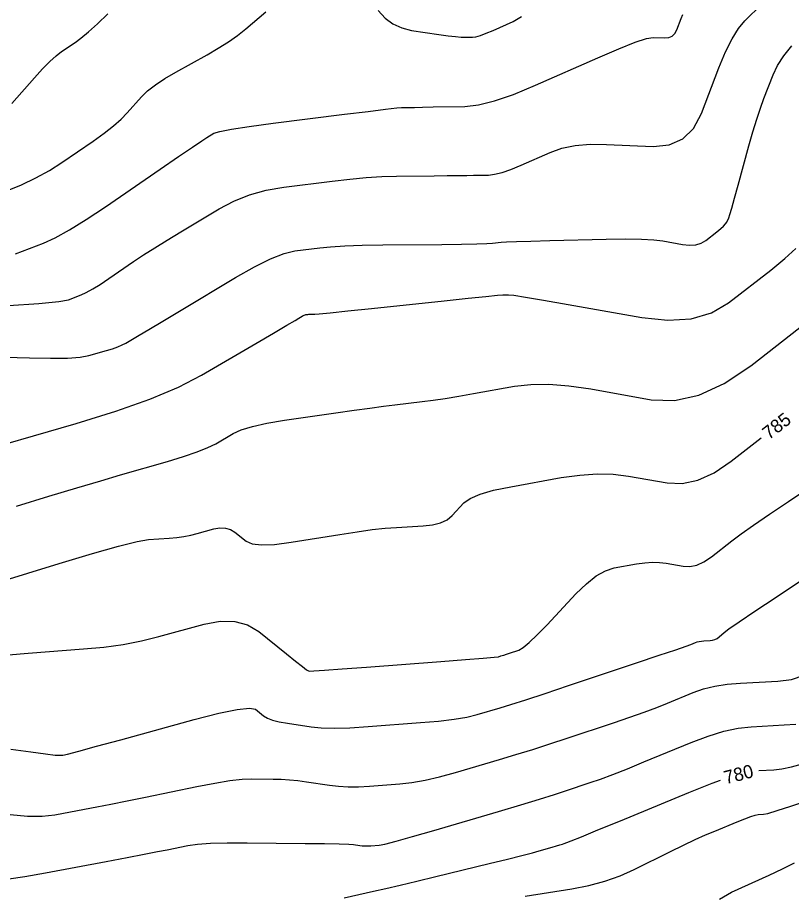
# Model space of a CAD drawing. Extents: x 2082232 to 2083549, y 592624 to 593832.
# Drawn here: x 2082483.95 to 2082524.73, y 592980.41 to 593026.54 of the extents above; entities that cross this region are included whole.
import ezdxf

# ---------------------------------------------------------------- set-up
doc = ezdxf.new("R2010")
doc.units = 0
doc.layers.add('DT_X_Contour_Major', color=7, linetype='Continuous')
doc.layers.add('DT_X_Contour_Minor', color=7, linetype='Continuous')

msp = doc.modelspace()

# ---------------------------------------------------------------- linework, layer by layer
at = {"layer": 'DT_X_Contour_Major'}
for points in [[(2082483.84, 593014.094), (2082485.31, 593014.662), (2082485.928, 593014.941), (2082486.679, 593015.353), (2082487.563, 593015.897), (2082488.579, 593016.575), (2082491.467, 593018.558), (2082492.433, 593019.219), (2082493.163, 593019.716), (2082493.659, 593020.048), (2082493.919, 593020.216), (2082494.299, 593020.444), (2082494.601, 593020.541), (2082495.22, 593020.661), (2082496.157, 593020.804), (2082497.412, 593020.97), (2082501.181, 593021.444), (2082502.429, 593021.599), (2082503.346, 593021.711), (2082503.931, 593021.778), (2082504.185, 593021.801), (2082504.42, 593021.803), (2082504.575, 593021.805), (2082504.866, 593021.81), (2082505.291, 593021.818), (2082505.852, 593021.829), (2082507.526, 593021.861), (2082508.23, 593021.939), (2082509.084, 593022.151), (2082510.089, 593022.495), (2082511.245, 593022.973), (2082514.528, 593024.423), (2082515.634, 593024.898), (2082516.49, 593025.234), (2082517.094, 593025.432), (2082517.448, 593025.491), (2082518.058, 593025.464), (2082518.269, 593025.484), (2082518.445, 593025.562), (2082518.585, 593025.699), (2082518.689, 593025.894), (2082518.921, 593026.494), (2082519.007, 593026.701)], [(2082480.935, 592996.196), (2082486.137, 592997.79), (2082487.895, 592998.316), (2082489.267, 592998.701), (2082490.253, 592998.944), (2082490.852, 592999.044), (2082491.937, 592999.124), (2082492.334, 592999.161), (2082492.713, 592999.214), (2082493.072, 592999.282), (2082493.413, 592999.365), (2082494.295, 592999.607), (2082494.613, 592999.664), (2082494.903, 592999.654), (2082495.165, 592999.577), (2082495.401, 592999.433), (2082495.992, 592998.958), (2082496.306, 592998.822), (2082496.806, 592998.768), (2082497.491, 592998.798), (2082498.361, 592998.912), (2082500.928, 592999.324), (2082501.837, 592999.463), (2082502.637, 592999.571), (2082503.329, 592999.646), (2082503.913, 592999.69), (2082505.325, 592999.765), (2082505.818, 592999.821), (2082506.236, 592999.932), (2082506.58, 593000.097), (2082506.849, 593000.318), (2082507.469, 593000.98), (2082507.797, 593001.219), (2082508.318, 593001.441), (2082509.03, 593001.646), (2082509.934, 593001.833), (2082512.603, 593002.309), (2082513.574, 593002.448), (2082514.487, 593002.509), (2082515.342, 593002.49), (2082516.139, 593002.393), (2082518.187, 593002.029), (2082518.973, 593001.998), (2082519.796, 593002.179), (2082520.656, 593002.572), (2082521.552, 593003.176), (2082523.125, 593004.398)], [(2082523.009, 592986.891), (2082523.804, 592986.932), (2082524.225, 592986.979), (2082524.726, 592987.081), (2082525.308, 592987.236)], [(2082501.161, 592980.185), (2082502.711, 592980.528), (2082503.352, 592980.672), (2082504.111, 592980.849), (2082504.99, 592981.058), (2082505.988, 592981.3), (2082508.807, 592981.986), (2082509.764, 592982.221), (2082510.521, 592982.41), (2082511.078, 592982.554), (2082511.434, 592982.652), (2082512.116, 592982.853), (2082512.347, 592982.921), (2082512.529, 592982.976), (2082512.661, 592983.016), (2082512.744, 592983.042), (2082512.898, 592983.094), (2082513.117, 592983.18), (2082513.661, 592983.401), (2082514.528, 592983.756), (2082515.718, 592984.245), (2082519.324, 592985.728), (2082520.555, 592986.217), (2082520.983, 592986.371)]]:
    msp.add_lwpolyline(points, dxfattribs=at)
at = {"layer": 'DT_X_Contour_Minor'}
for points in [[(2082483.473, 593011.367), (2082485.063, 593011.476), (2082486.117, 593011.579), (2082486.634, 593011.678), (2082487.295, 593011.933), (2082487.573, 593012.059), (2082487.911, 593012.244), (2082488.308, 593012.489), (2082488.766, 593012.794), (2082490.065, 593013.686), (2082490.586, 593014.036), (2082491.175, 593014.415), (2082491.83, 593014.823), (2082492.553, 593015.261), (2082494.569, 593016.467), (2082495.35, 593016.878), (2082496.18, 593017.205), (2082497.058, 593017.45), (2082497.986, 593017.611), (2082500.526, 593017.93), (2082501.452, 593018.036), (2082502.327, 593018.114), (2082503.149, 593018.163), (2082503.92, 593018.185), (2082505.907, 593018.205), (2082506.595, 593018.213), (2082507.17, 593018.219), (2082507.632, 593018.226), (2082507.98, 593018.232), (2082508.758, 593018.246), (2082509.084, 593018.283), (2082509.481, 593018.381), (2082509.948, 593018.541), (2082510.485, 593018.763), (2082512.009, 593019.437), (2082512.625, 593019.652), (2082513.327, 593019.795), (2082514.116, 593019.865), (2082514.992, 593019.861), (2082517.444, 593019.753), (2082518.293, 593019.83), (2082518.998, 593020.144), (2082519.561, 593020.695), (2082519.981, 593021.481), (2082520.911, 593023.893), (2082521.257, 593024.726), (2082521.6, 593025.414), (2082521.94, 593025.959), (2082522.275, 593026.36), (2082523.164, 593027.236)], [(2082483.326, 593017.39), (2082484.151, 593017.732), (2082484.918, 593018.098), (2082485.625, 593018.488), (2082486.275, 593018.901), (2082487.928, 593020.037), (2082488.506, 593020.448), (2082488.999, 593020.832), (2082489.407, 593021.189), (2082489.73, 593021.517), (2082490.479, 593022.356), (2082490.803, 593022.674), (2082491.211, 593022.998), (2082491.704, 593023.33), (2082492.282, 593023.668), (2082493.935, 593024.578), (2082494.528, 593024.919), (2082495.064, 593025.26), (2082495.545, 593025.599), (2082495.971, 593025.937), (2082497.031, 593026.838)], [(2082502.957, 593026.905), (2082503.32, 593026.509), (2082503.733, 593026.204), (2082504.196, 593025.989), (2082504.709, 593025.865), (2082506.143, 593025.652), (2082506.633, 593025.583), (2082507.026, 593025.534), (2082507.322, 593025.506), (2082507.521, 593025.499), (2082507.922, 593025.506), (2082508.104, 593025.531), (2082508.346, 593025.598), (2082508.648, 593025.708), (2082509.012, 593025.86), (2082510.063, 593026.325), (2082510.507, 593026.601)], [(2082483.657, 593022.008), (2082484.847, 593023.365), (2082485.271, 593023.833), (2082485.65, 593024.218), (2082485.984, 593024.522), (2082486.273, 593024.743), (2082486.984, 593025.222), (2082487.292, 593025.452), (2082487.682, 593025.78), (2082488.156, 593026.207), (2082488.713, 593026.733)], [(2082481.32, 593008.711), (2082484.578, 593008.613), (2082485.69, 593008.593), (2082486.582, 593008.607), (2082487.256, 593008.656), (2082487.71, 593008.738), (2082488.628, 593009.002), (2082488.951, 593009.101), (2082489.228, 593009.199), (2082489.46, 593009.297), (2082489.647, 593009.394), (2082490.086, 593009.651), (2082490.364, 593009.816), (2082490.87, 593010.117), (2082491.603, 593010.555), (2082492.564, 593011.129), (2082495.429, 593012.844), (2082496.431, 593013.414), (2082497.287, 593013.839), (2082497.997, 593014.118), (2082498.561, 593014.253), (2082499.87, 593014.417), (2082500.446, 593014.473), (2082501.191, 593014.516), (2082502.106, 593014.546), (2082503.19, 593014.565), (2082506.306, 593014.596), (2082507.349, 593014.609), (2082508.143, 593014.623), (2082508.686, 593014.639), (2082508.979, 593014.656), (2082509.426, 593014.703), (2082509.712, 593014.722), (2082510.235, 593014.744), (2082510.994, 593014.767), (2082511.989, 593014.792), (2082514.958, 593014.863), (2082515.98, 593014.878), (2082516.821, 593014.869), (2082517.481, 593014.836), (2082517.959, 593014.779), (2082518.993, 593014.595), (2082519.359, 593014.556), (2082519.685, 593014.578), (2082519.968, 593014.66), (2082520.211, 593014.802), (2082520.802, 593015.261), (2082521.001, 593015.422), (2082521.153, 593015.561), (2082521.26, 593015.677), (2082521.32, 593015.771), (2082521.421, 593015.993), (2082521.48, 593016.163), (2082521.584, 593016.506), (2082521.731, 593017.023), (2082521.923, 593017.714), (2082522.492, 593019.786), (2082522.702, 593020.524), (2082522.903, 593021.185), (2082523.095, 593021.769), (2082523.28, 593022.276), (2082523.761, 593023.524), (2082523.992, 593024.006), (2082524.324, 593024.514), (2082524.757, 593025.049)], [(2082481.068, 593003.442), (2082487.035, 593005.16), (2082489.126, 593005.802), (2082490.926, 593006.439), (2082492.433, 593007.073), (2082493.649, 593007.702), (2082496.501, 593009.373), (2082497.445, 593009.926), (2082498.138, 593010.332), (2082498.58, 593010.592), (2082498.77, 593010.704), (2082498.945, 593010.809), (2082499.006, 593010.843), (2082499.058, 593010.869), (2082499.101, 593010.886), (2082499.135, 593010.894), (2082499.215, 593010.904), (2082499.25, 593010.908), (2082499.295, 593010.91), (2082499.351, 593010.912), (2082499.416, 593010.913), (2082499.606, 593010.915), (2082499.847, 593010.935), (2082500.428, 593010.992), (2082501.349, 593011.088), (2082502.609, 593011.221), (2082506.425, 593011.627), (2082507.691, 593011.76), (2082508.628, 593011.856), (2082509.235, 593011.915), (2082509.514, 593011.937), (2082509.817, 593011.944), (2082510.099, 593011.914), (2082510.716, 593011.819), (2082511.669, 593011.658), (2082512.957, 593011.432), (2082516.84, 593010.741), (2082518.219, 593010.596), (2082519.441, 593010.676), (2082520.508, 593010.984), (2082521.419, 593011.518), (2082523.64, 593013.243), (2082524.387, 593013.848), (2082524.961, 593014.37)], [(2082483.898, 593000.806), (2082485.6, 593001.326), (2082487.08, 593001.773), (2082488.339, 593002.148), (2082489.377, 593002.451), (2082491.848, 593003.162), (2082492.702, 593003.421), (2082493.41, 593003.663), (2082493.973, 593003.889), (2082494.389, 593004.098), (2082495.306, 593004.636), (2082495.733, 593004.83), (2082496.328, 593005.011), (2082497.091, 593005.178), (2082498.021, 593005.331), (2082500.725, 593005.722), (2082501.68, 593005.858), (2082502.516, 593005.974), (2082503.233, 593006.069), (2082503.832, 593006.144), (2082505.271, 593006.316), (2082505.845, 593006.39), (2082506.486, 593006.485), (2082507.195, 593006.599), (2082507.972, 593006.734), (2082510.134, 593007.119), (2082510.993, 593007.219), (2082511.949, 593007.23), (2082513.001, 593007.151), (2082514.15, 593006.983), (2082517.343, 593006.415), (2082518.569, 593006.368), (2082519.852, 593006.65), (2082521.192, 593007.262), (2082522.589, 593008.204), (2082526.391, 593011.157)], [(2082483.473, 592992.983), (2082484.502, 592993.075), (2082487.424, 592993.288), (2082488.495, 592993.389), (2082489.515, 592993.531), (2082490.483, 592993.714), (2082491.4, 592993.938), (2082493.779, 592994.591), (2082494.628, 592994.75), (2082495.391, 592994.738), (2082496.068, 592994.555), (2082496.659, 592994.2), (2082498.12, 592993.026), (2082498.603, 592992.641), (2082498.957, 592992.364), (2082499.18, 592992.196), (2082499.273, 592992.138), (2082499.349, 592992.126), (2082499.557, 592992.136), (2082500.126, 592992.175), (2082501.055, 592992.242), (2082502.344, 592992.338), (2082506.262, 592992.633), (2082507.554, 592992.731), (2082508.49, 592992.805), (2082509.07, 592992.855), (2082509.294, 592992.881), (2082509.419, 592992.918), (2082509.482, 592992.937), (2082509.579, 592992.968), (2082509.71, 592993.012), (2082509.875, 592993.066), (2082510.358, 592993.228), (2082510.587, 592993.357), (2082510.914, 592993.622), (2082511.337, 592994.025), (2082511.857, 592994.564), (2082513.374, 592996.184), (2082513.926, 592996.725), (2082514.447, 592997.135), (2082514.936, 592997.411), (2082515.393, 592997.556), (2082516.569, 592997.766), (2082516.998, 592997.827), (2082517.4, 592997.854), (2082517.777, 592997.846), (2082518.128, 592997.803), (2082519.031, 592997.643), (2082519.378, 592997.629), (2082519.74, 592997.709), (2082520.119, 592997.882), (2082520.514, 592998.148), (2082521.589, 592998.983), (2082522.077, 592999.347), (2082522.736, 592999.814), (2082523.566, 593000.383), (2082524.566, 593001.055), (2082527.46, 593002.983)], [(2082483.601, 592988.009), (2082484.655, 592987.865), (2082485.43, 592987.763), (2082485.924, 592987.704), (2082486.138, 592987.688), (2082486.335, 592987.703), (2082486.581, 592987.757), (2082487.172, 592987.91), (2082488.108, 592988.161), (2082489.388, 592988.511), (2082493.262, 592989.575), (2082494.554, 592989.908), (2082495.522, 592990.109), (2082496.166, 592990.178), (2082496.488, 592990.116), (2082496.914, 592989.773), (2082497.112, 592989.652), (2082497.388, 592989.545), (2082497.74, 592989.453), (2082498.168, 592989.375), (2082499.414, 592989.186), (2082499.952, 592989.134), (2082500.632, 592989.119), (2082501.454, 592989.141), (2082502.418, 592989.2), (2082505.177, 592989.408), (2082506.139, 592989.492), (2082506.957, 592989.591), (2082507.631, 592989.705), (2082508.16, 592989.832), (2082509.378, 592990.191), (2082509.945, 592990.365), (2082510.735, 592990.617), (2082511.747, 592990.949), (2082512.981, 592991.359), (2082516.567, 592992.557), (2082517.754, 592992.955), (2082518.628, 592993.25), (2082519.188, 592993.441), (2082519.434, 592993.53), (2082519.672, 592993.627), (2082519.766, 592993.66), (2082519.87, 592993.686), (2082519.983, 592993.704), (2082520.107, 592993.714), (2082520.45, 592993.732), (2082520.575, 592993.749), (2082520.694, 592993.786), (2082520.807, 592993.845), (2082520.913, 592993.924), (2082521.189, 592994.163), (2082521.437, 592994.347), (2082521.974, 592994.718), (2082522.8, 592995.276), (2082523.915, 592996.021), (2082527.275, 592998.259)], [(2082483.565, 592984.563), (2082484.474, 592984.487), (2082485.254, 592984.486), (2082485.907, 592984.559), (2082487.477, 592984.854), (2082488.119, 592984.977), (2082488.868, 592985.124), (2082489.724, 592985.295), (2082490.686, 592985.491), (2082493.396, 592986.045), (2082494.338, 592986.226), (2082495.133, 592986.354), (2082495.78, 592986.429), (2082496.279, 592986.452), (2082497.413, 592986.44), (2082497.842, 592986.427), (2082498.278, 592986.399), (2082498.721, 592986.354), (2082499.172, 592986.293), (2082500.383, 592986.11), (2082500.856, 592986.055), (2082501.365, 592986.029), (2082501.91, 592986.031), (2082502.492, 592986.062), (2082504.092, 592986.183), (2082504.725, 592986.254), (2082505.425, 592986.378), (2082506.192, 592986.554), (2082507.025, 592986.783), (2082509.337, 592987.464), (2082510.209, 592987.725), (2082511.095, 592988), (2082511.992, 592988.287), (2082512.902, 592988.587), (2082515.344, 592989.403), (2082516.209, 592989.697), (2082516.972, 592989.967), (2082517.635, 592990.213), (2082518.196, 592990.435), (2082519.556, 592990.994), (2082520.094, 592991.183), (2082520.689, 592991.328), (2082521.34, 592991.431), (2082522.047, 592991.49), (2082524.008, 592991.591), (2082524.725, 592991.689), (2082525.407, 592991.905)], [(2082483.483, 592981.184), (2082484.338, 592981.306), (2082485.423, 592981.497), (2082488.618, 592982.097), (2082489.718, 592982.305), (2082490.621, 592982.477), (2082491.326, 592982.614), (2082491.835, 592982.715), (2082492.927, 592982.939), (2082493.429, 592983.011), (2082494.116, 592983.058), (2082494.987, 592983.082), (2082496.043, 592983.082), (2082499.105, 592983.05), (2082500.125, 592983.037), (2082500.889, 592983.022), (2082501.398, 592983.006), (2082501.651, 592982.988), (2082501.985, 592982.937), (2082502.115, 592982.922), (2082502.255, 592982.915), (2082502.406, 592982.916), (2082502.566, 592982.924), (2082503.007, 592982.957), (2082503.311, 592983.015), (2082503.893, 592983.164), (2082504.753, 592983.404), (2082505.891, 592983.734), (2082509.295, 592984.737), (2082510.474, 592985.086), (2082511.454, 592985.382), (2082512.237, 592985.625), (2082512.823, 592985.814), (2082514.121, 592986.248), (2082514.663, 592986.439), (2082515.317, 592986.684), (2082516.081, 592986.984), (2082516.957, 592987.34), (2082519.44, 592988.361), (2082520.337, 592988.701), (2082521.163, 592988.953), (2082521.92, 592989.117), (2082522.608, 592989.195), (2082524.348, 592989.285), (2082524.958, 592989.327)], [(2082510.703, 592980.264), (2082513.159, 592980.658), (2082514.054, 592980.831), (2082514.9, 592981.057), (2082515.695, 592981.336), (2082516.439, 592981.668), (2082518.357, 592982.622), (2082519.042, 592982.957), (2082519.658, 592983.249), (2082520.205, 592983.498), (2082520.684, 592983.702), (2082521.867, 592984.189), (2082522.269, 592984.349), (2082522.587, 592984.466), (2082522.822, 592984.538), (2082522.972, 592984.565), (2082523.261, 592984.58), (2082523.492, 592984.631), (2082523.971, 592984.774), (2082524.697, 592985.007), (2082525.67, 592985.332)], [(2082520.931, 592980.105), (2082521.578, 592980.484), (2082523.559, 592981.377), (2082524.265, 592981.709), (2082524.895, 592982.034)]]:
    msp.add_lwpolyline(points, dxfattribs=at)

# ---------------------------------------------------------------- texts
at = {"layer": 'DT_X_Contour_Major'}
for s, rotation, p in [('785', 37.6834, (2082523.542, 593004.281)), ('780', 14.4006, (2082521.271, 592986.159))]:
    msp.add_text(s, height=0.7, rotation=rotation, dxfattribs=at).set_placement(p)

doc.saveas('drawing.dxf')
